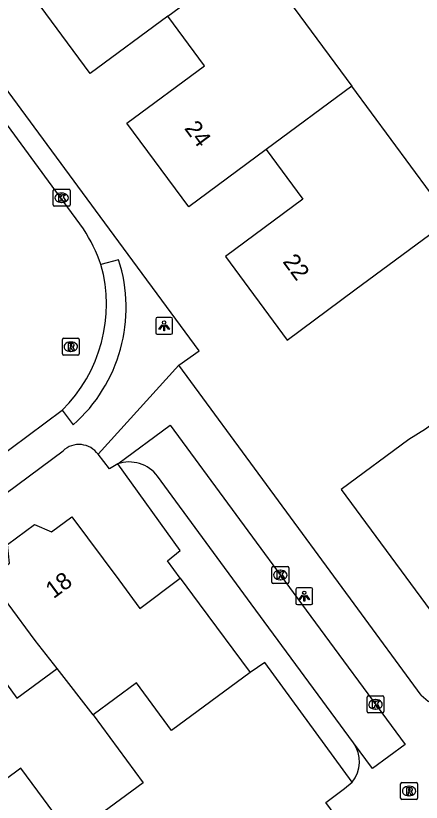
# Model space of a CAD drawing. Extents: x 163427 to 164190, y 380331 to 381641.
# Drawn here: x 163764.91 to 163788.94, y 381238.24 to 381284.84 of the extents above; entities that cross this region are included whole.
import ezdxf

# ---------------------------------------------------------------- set-up
doc = ezdxf.new("R2010")
doc.units = 0
for name, color, linetype in [('IMGEO_Fietspad_open', 7, 'Continuous'), ('IMGEO_Groenvoorziening', 7, 'Continuous'), ('IMGEO_Kolk', 7, 'Continuous'), ('IMGEO_Lichtpunt', 7, 'Continuous'), ('IMGEO_Pand', 7, 'Continuous'), ('IMGEO_Pand_nummerreeks', 7, 'Continuous'), ('IMGEO_Rijbaan_lokaal_open', 7, 'Continuous'), ('IMGEO_Rioolput', 7, 'Continuous'), ('IMGEO_Voetpad_open', 7, 'Continuous')]:
    doc.layers.add(name, color=color, linetype=linetype)

msp = doc.modelspace()

# ---------------------------------------------------------------- linework, layer by layer
at = {"layer": 'IMGEO_Fietspad_open'}
for points in [[(163770.95, 381258.29), (163774.054, 381260.587), (163781.847, 381250), (163787.983, 381241.663), (163786.044, 381240.238), (163784.925, 381241.758)], [(163784.925, 381241.758), (163778.866, 381250), (163773.313, 381257.553)]]:
    msp.add_lwpolyline(points, dxfattribs=at)
msp.add_arc((163771.622, 381256.288), 2.112, 36.7949, 108.5605, dxfattribs=at)
at = {"layer": 'IMGEO_Groenvoorziening'}
for points in [[(163774.663, 381251.508), (163773.896, 381252.542), (163774.655, 381253.158), (163770.95, 381258.29)], [(163784.841, 381239.434), (163779.677, 381246.519), (163778.797, 381245.933)]]:
    msp.add_lwpolyline(points, dxfattribs=at)
at = {"layer": 'IMGEO_Kolk'}
for p, q in [((163767.133, 381273.626), (163767.133, 381274.478)), ((163767.208, 381274.552), (163768.06, 381274.552)), ((163767.621, 381274.332), (163767.646, 381274.332)), ((163768.134, 381274.478), (163768.134, 381273.626)), ((163767.644, 381273.772), (163767.619, 381273.772)), ((163768.06, 381273.552), (163767.208, 381273.552)), ((163780.086, 381251.277), (163780.086, 381252.129)), ((163780.161, 381252.203), (163781.013, 381252.203)), ((163780.574, 381251.983), (163780.599, 381251.983)), ((163781.087, 381252.129), (163781.087, 381251.277)), ((163780.597, 381251.423), (163780.572, 381251.423)), ((163781.013, 381251.203), (163780.161, 381251.203)), ((163785.732, 381243.613), (163785.732, 381244.465)), ((163785.807, 381244.539), (163786.659, 381244.539)), ((163786.22, 381244.319), (163786.245, 381244.319)), ((163786.733, 381244.465), (163786.733, 381243.613)), ((163786.659, 381243.539), (163785.807, 381243.539)), ((163786.243, 381243.759), (163786.218, 381243.759))]:
    msp.add_line(p, q, dxfattribs=at)
for points in [[(163767.133, 381273.626), (163767.133, 381274.478)], [(163767.208, 381274.552), (163768.06, 381274.552)], [(163767.454, 381274.252), (163767.577, 381274.252), (163767.577, 381274.101), (163767.707, 381274.252), (163767.871, 381274.252), (163767.725, 381274.101), (163767.878, 381273.852), (163767.726, 381273.852), (163767.641, 381274.016), (163767.577, 381273.949), (163767.577, 381273.852), (163767.454, 381273.852), (163767.454, 381274.252)], [(163768.134, 381274.478), (163768.134, 381273.626)], [(163768.06, 381273.552), (163767.208, 381273.552)], [(163780.086, 381251.277), (163780.086, 381252.129)], [(163780.161, 381252.203), (163781.013, 381252.203)], [(163780.407, 381251.903), (163780.53, 381251.903), (163780.53, 381251.752), (163780.66, 381251.903), (163780.824, 381251.903), (163780.678, 381251.752), (163780.831, 381251.503), (163780.679, 381251.503), (163780.594, 381251.667), (163780.53, 381251.6), (163780.53, 381251.503), (163780.407, 381251.503), (163780.407, 381251.903)], [(163781.087, 381252.129), (163781.087, 381251.277)], [(163781.013, 381251.203), (163780.161, 381251.203)], [(163785.732, 381243.613), (163785.732, 381244.465)], [(163785.807, 381244.539), (163786.659, 381244.539)], [(163786.733, 381244.465), (163786.733, 381243.613)], [(163786.053, 381244.239), (163786.176, 381244.239), (163786.176, 381244.088), (163786.306, 381244.239), (163786.47, 381244.239), (163786.324, 381244.088), (163786.477, 381243.839), (163786.325, 381243.839), (163786.24, 381244.003), (163786.176, 381243.936), (163786.176, 381243.839), (163786.053, 381243.839), (163786.053, 381244.239)], [(163786.659, 381243.539), (163785.807, 381243.539)]]:
    msp.add_lwpolyline(points, dxfattribs=at)
for centre, start, end in [((163767.21, 381274.476), 91.552, 178.448), ((163767.21, 381274.476), 91.552, 178.448), ((163768.058, 381274.476), 1.552, 88.448), ((163768.058, 381274.476), 1.552, 88.448), ((163767.21, 381273.628), 181.552, 268.448), ((163767.21, 381273.628), 181.552, 268.448), ((163768.058, 381273.628), 271.552, 358.448), ((163768.058, 381273.628), 271.552, 358.448), ((163780.163, 381252.127), 91.552, 178.448), ((163780.163, 381252.127), 91.552, 178.448), ((163781.011, 381252.127), 1.552, 88.448), ((163781.011, 381252.127), 1.552, 88.448), ((163780.163, 381251.279), 181.552, 268.448), ((163780.163, 381251.279), 181.552, 268.448), ((163781.011, 381251.279), 271.552, 358.448), ((163781.011, 381251.279), 271.552, 358.448), ((163785.809, 381244.463), 91.552, 178.448), ((163785.809, 381244.463), 91.552, 178.448), ((163786.657, 381244.463), 1.552, 88.448), ((163786.657, 381244.463), 1.552, 88.448), ((163785.809, 381243.615), 181.552, 268.448), ((163785.809, 381243.615), 181.552, 268.448), ((163786.657, 381243.615), 271.552, 358.448), ((163786.657, 381243.615), 271.552, 358.448)]:
    msp.add_arc(centre, 0.0765, start, end, dxfattribs=at)
for centre, major_axis, ratio, start_param, end_param in [((163767.62, 381274.052), (-0.387, 0.002), 0.722429, 4.712389, 7.853982), ((163767.645, 381274.052), (-0.39, 0.002), 0.717154, 1.570796, 4.712389), ((163780.573, 381251.703), (-0.387, 0.002), 0.722429, 4.712389, 7.853982), ((163780.598, 381251.703), (-0.39, 0.002), 0.717154, 1.570796, 4.712389), ((163786.219, 381244.039), (-0.387, 0.002), 0.722429, 4.712389, 7.853982), ((163786.244, 381244.039), (-0.39, 0.002), 0.717154, 1.570796, 4.712389)]:
    msp.add_ellipse(centre, major_axis=major_axis, ratio=ratio, start_param=start_param, end_param=end_param, dxfattribs=at)
at = {"layer": 'IMGEO_Lichtpunt'}
for p, q in [((163773.205, 381266.865), (163773.205, 381266.058)), ((163773.205, 381266.865), (163773.205, 381266.058)), ((163774.107, 381266.96), (163773.299, 381266.96)), ((163774.107, 381266.96), (163773.299, 381266.96)), ((163774.201, 381266.058), (163774.201, 381266.865)), ((163774.201, 381266.058), (163774.201, 381266.865)), ((163773.299, 381265.964), (163774.107, 381265.964)), ((163773.299, 381265.964), (163774.107, 381265.964)), ((163781.51, 381250.85), (163781.51, 381250.043)), ((163781.51, 381250.85), (163781.51, 381250.043)), ((163782.412, 381250.945), (163781.604, 381250.945)), ((163782.412, 381250.945), (163781.604, 381250.945)), ((163782.506, 381250.043), (163782.506, 381250.85)), ((163782.506, 381250.043), (163782.506, 381250.85)), ((163781.604, 381249.949), (163782.412, 381249.949)), ((163781.604, 381249.949), (163782.412, 381249.949))]:
    msp.add_line(p, q, dxfattribs=at)
for points in [[(163773.579, 381266.529), (163773.618, 381266.501), (163773.43, 381266.239), (163773.392, 381266.266), (163773.579, 381266.529)], [(163773.681, 381266.481), (163773.728, 381266.481), (163773.728, 381266.159), (163773.681, 381266.159), (163773.681, 381266.481)], [(163773.791, 381266.501), (163773.829, 381266.528), (163774.016, 381266.266), (163773.977, 381266.238), (163773.791, 381266.501)], [(163781.884, 381250.514), (163781.923, 381250.486), (163781.735, 381250.224), (163781.697, 381250.251), (163781.884, 381250.514)], [(163781.986, 381250.466), (163782.033, 381250.466), (163782.033, 381250.144), (163781.986, 381250.144), (163781.986, 381250.466)], [(163782.096, 381250.486), (163782.134, 381250.513), (163782.321, 381250.251), (163782.282, 381250.223), (163782.096, 381250.486)]]:
    msp.add_lwpolyline(points, dxfattribs=at)
for centre in [(163773.704, 381266.663), (163782.009, 381250.648)]:
    msp.add_circle(centre, 0.0994, dxfattribs=at)
for centre, start, end in [((163773.299, 381266.865), 90, 180), ((163773.299, 381266.865), 90, 180), ((163774.107, 381266.865), 0, 90), ((163774.107, 381266.865), 0, 90), ((163773.299, 381266.058), 180, 270), ((163773.299, 381266.058), 180, 270), ((163774.107, 381266.058), 270, 0), ((163774.107, 381266.058), 270, 360), ((163781.604, 381250.85), 90, 180), ((163781.604, 381250.85), 90, 180), ((163782.412, 381250.85), 0, 90), ((163782.412, 381250.85), 0, 90), ((163781.604, 381250.043), 180, 270), ((163781.604, 381250.043), 180, 270), ((163782.412, 381250.043), 270, 0), ((163782.412, 381250.043), 270, 360)]:
    msp.add_arc(centre, 0.0946, start, end, dxfattribs=at)
at = {"layer": 'IMGEO_Pand'}
for points in [[(163773.913, 381284.805), (163769.327, 381281.42), (163765.681, 381286.36), (163770.267, 381289.745), (163768.094, 381292.689)], [(163773.913, 381284.805), (163778.992, 381288.563)], [(163778.992, 381288.563), (163784.829, 381280.656)], [(163779.744, 381276.905), (163775.159, 381273.52), (163771.501, 381278.476), (163776.086, 381281.861), (163773.913, 381284.805)], [(163779.744, 381276.905), (163781.918, 381273.96), (163777.332, 381270.576), (163780.99, 381265.62), (163785.013, 381268.59), (163790.659, 381272.757), (163784.829, 381280.656)], [(163784.829, 381280.656), (163779.744, 381276.905)], [(163791.992, 381262.44), (163789.191, 381260.34), (163788.207, 381259.739), (163784.19, 381256.76), (163789.2, 381250), (163791.32, 381247.14), (163795.184, 381250), (163796.256, 381250.793), (163792.871, 381255.368), (163795.696, 381257.459)], [(163767.358, 381246.156), (163766.061, 381247.821), (163764.456, 381250), (163763.334, 381251.523), (163764.531, 381252.412), (163764.416, 381253.509), (163766.011, 381254.689), (163767.021, 381254.26), (163768.228, 381255.156), (163771.01, 381251.413), (163772.265, 381249.725), (163774.663, 381251.508)], [(163774.663, 381251.508), (163775.781, 381250), (163778.797, 381245.933)], [(163760.154, 381240.746), (163758.827, 381242.444), (163756.091, 381246.159), (163757.288, 381247.048), (163757.173, 381248.145), (163758.768, 381249.325), (163759.778, 381248.896), (163761, 381249.804), (163763.727, 381246.102), (163764.979, 381244.403), (163767.358, 381246.156)], [(163769.489, 381243.418), (163767.358, 381246.156)], [(163778.797, 381245.933), (163774.139, 381242.5), (163772.064, 381245.315), (163769.489, 381243.418)], [(163769.489, 381243.418), (163772.454, 381239.395), (163768.43, 381236.429), (163768.183, 381236.247), (163765.218, 381240.269), (163762.241, 381238.075)]]:
    msp.add_lwpolyline(points, dxfattribs=at)
at = {"layer": 'IMGEO_Rijbaan_lokaal_open'}
for points in [[(163768.931, 381272.214), (163766.855, 381275.036), (163764.63, 381278.054), (163761.048, 381282.907), (163758.816, 381285.926), (163755.171, 381290.857)], [(163737.769, 381239.302), (163743.166, 381243.303), (163746.197, 381245.539), (163750.571, 381248.802), (163752.181, 381250), (163753.605, 381251.059), (163757.64, 381254.032), (163760.666, 381256.281), (163764.646, 381259.224), (163767.663, 381261.473)]]:
    msp.add_lwpolyline(points, dxfattribs=at)
for centre, radius, start, end in [((163759.321, 381266.247), 11.312, 19.8606, 31.8363), ((163761.482, 381267.735), 8.799, 314.627, 15.5209)]:
    msp.add_arc(centre, radius, start, end, dxfattribs=at)
at = {"layer": 'IMGEO_Rioolput'}
for p, q in [((163767.67, 381264.801), (163767.67, 381265.653)), ((163767.745, 381265.727), (163768.597, 381265.727)), ((163768.158, 381265.507), (163768.183, 381265.507)), ((163768.671, 381265.653), (163768.671, 381264.801)), ((163768.181, 381264.947), (163768.156, 381264.947)), ((163768.597, 381264.727), (163767.745, 381264.727)), ((163787.721, 381238.478), (163787.721, 381239.33)), ((163787.796, 381239.404), (163788.648, 381239.404)), ((163788.722, 381239.33), (163788.722, 381238.478)), ((163788.209, 381239.184), (163788.234, 381239.184)), ((163788.648, 381238.404), (163787.796, 381238.404)), ((163788.232, 381238.624), (163788.207, 381238.624))]:
    msp.add_line(p, q, dxfattribs=at)
for points in [[(163767.67, 381264.801), (163767.67, 381265.653)], [(163767.745, 381265.727), (163768.597, 381265.727)], [(163768.259, 381265.425), (163768.007, 381265.427), (163768.007, 381265.027)], [(163768.185, 381265.346), (163768.131, 381265.346), (163768.131, 381265.265)], [(163768.671, 381265.653), (163768.671, 381264.801)], [(163768.007, 381265.027), (163768.131, 381265.027), (163768.131, 381265.189), (163768.142, 381265.189)], [(163768.131, 381265.265), (163768.183, 381265.265)], [(163768.189, 381265.16), (163768.26, 381265.027), (163768.4, 381265.027), (163768.335, 381265.153)], [(163768.597, 381264.727), (163767.745, 381264.727)], [(163787.721, 381238.478), (163787.721, 381239.33)], [(163787.796, 381239.404), (163788.648, 381239.404)], [(163788.722, 381239.33), (163788.722, 381238.478)], [(163788.31, 381239.102), (163788.058, 381239.104), (163788.058, 381238.704)], [(163788.058, 381238.704), (163788.182, 381238.704), (163788.182, 381238.866), (163788.193, 381238.866)], [(163788.236, 381239.023), (163788.182, 381239.023), (163788.182, 381238.942)], [(163788.182, 381238.942), (163788.234, 381238.942)], [(163788.24, 381238.837), (163788.311, 381238.704), (163788.451, 381238.704), (163788.386, 381238.83)], [(163788.648, 381238.404), (163787.796, 381238.404)]]:
    msp.add_lwpolyline(points, dxfattribs=at)
for centre, radius, start, end in [((163767.747, 381265.651), 0.0765, 91.552, 178.448), ((163767.747, 381265.651), 0.0765, 91.552, 178.448), ((163768.191, 381265.25), 0.0964, 77.0061, 93.1865), ((163768.205, 381265.307), 0.0378, 276.6634, 79.6772), ((163768.258, 381265.315), 0.109, 350.3612, 89.416), ((163768.256, 381265.315), 0.112, 277.5842, 350.9817), ((163768.595, 381265.651), 0.0765, 1.552, 88.448), ((163768.595, 381265.651), 0.0765, 1.552, 88.448), ((163768.141, 381265.136), 0.0533, 26.0293, 88.6989), ((163768.167, 381265.454), 0.19, 274.7715, 282.9687), ((163768.24, 381265.1), 0.108, 29.5134, 73.7905), ((163767.747, 381264.803), 0.0765, 181.552, 268.448), ((163767.747, 381264.803), 0.0765, 181.552, 268.448), ((163768.595, 381264.803), 0.0765, 271.552, 358.448), ((163768.595, 381264.803), 0.0765, 271.552, 358.448), ((163787.798, 381239.328), 0.0765, 91.552, 178.448), ((163787.798, 381239.328), 0.0765, 91.552, 178.448), ((163788.646, 381239.328), 0.0765, 1.552, 88.448), ((163788.646, 381239.328), 0.0765, 1.552, 88.448), ((163788.192, 381238.813), 0.0533, 26.0293, 88.6989), ((163788.218, 381239.131), 0.19, 274.7715, 282.9687), ((163788.242, 381238.927), 0.0964, 77.0061, 93.1865), ((163788.256, 381238.984), 0.0378, 276.6634, 79.6772), ((163788.309, 381238.992), 0.109, 350.3612, 89.416), ((163788.307, 381238.992), 0.112, 277.5842, 350.9817), ((163788.291, 381238.777), 0.108, 29.5134, 73.7905), ((163787.798, 381238.48), 0.0765, 181.552, 268.448), ((163787.798, 381238.48), 0.0765, 181.552, 268.448), ((163788.646, 381238.48), 0.0765, 271.552, 358.448), ((163788.646, 381238.48), 0.0765, 271.552, 358.448)]:
    msp.add_arc(centre, radius, start, end, dxfattribs=at)
for centre, major_axis, ratio, start_param, end_param in [((163768.157, 381265.227), (-0.387, 0.002), 0.722429, 4.712389, 7.853982), ((163768.182, 381265.227), (-0.39, 0.002), 0.717154, 1.570796, 4.712389), ((163788.208, 381238.904), (-0.387, 0.002), 0.722429, 4.712389, 7.853982), ((163788.233, 381238.904), (-0.39, 0.002), 0.717154, 1.570796, 4.712389)]:
    msp.add_ellipse(centre, major_axis=major_axis, ratio=ratio, start_param=start_param, end_param=end_param, dxfattribs=at)
at = {"layer": 'IMGEO_Voetpad_open'}
for points in [[(163774.583, 381264.129), (163775.788, 381264.982), (163769.92, 381272.943), (163755.631, 381292.33)], [(163771.007, 381270.382), (163769.96, 381270.09)], [(163769.795, 381258.853), (163774.583, 381264.129)], [(163788.937, 381244.592), (163784.964, 381250), (163774.583, 381264.129)], [(163767.663, 381261.473), (163768.316, 381260.601)], [(163738.486, 381237.379), (163755.493, 381250), (163767.711, 381259.062)], [(163770.95, 381258.29), (163770.469, 381257.992), (163769.795, 381258.853)], [(163832.5, 381173.217), (163831.667, 381172.644), (163783.277, 381238.221), (163784.4, 381239.055), (163784.841, 381239.434)]]:
    msp.add_lwpolyline(points, dxfattribs=at)
for centre, radius, start, end in [((163762.186, 381267.548), 9.265, 311.4234, 17.8108), ((163768.661, 381258.036), 1.398, 35.7635, 132.7827), ((163790.431, 381245.914), 1.995, 221.51, 304.1374), ((163783.4, 381240.65), 1.885, 319.853, 36.007)]:
    msp.add_arc(centre, radius, start, end, dxfattribs=at)

# ---------------------------------------------------------------- texts
at = {"layer": 'IMGEO_Pand_nummerreeks'}
for s, rotation, p in [('24', 306.4309, (163774.867, 381278.159)), ('22', 306.4309, (163780.696, 381270.262)), ('18', 36.5891, (163767.149, 381250.269))]:
    msp.add_text(s, height=1, rotation=rotation, dxfattribs=at).set_placement(p)

doc.saveas('drawing.dxf')
